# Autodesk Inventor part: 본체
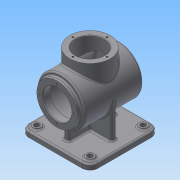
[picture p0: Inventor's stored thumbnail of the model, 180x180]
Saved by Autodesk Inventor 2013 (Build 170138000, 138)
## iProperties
Created: 2015-07
Part Number: 본체
Material: 일반
Document SubType Name: Modeling
Designer: ST5
Density: 1 g/cm^3
Author: ST5
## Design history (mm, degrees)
sketch "스케치1"
  geometry: L1 (-65, 65)-(65, 65); L2 (65, 65)-(65, -65); L3 (65, -65)-(-65, -65); L4 (-65, -65)-(-65, 65); 1 further point
  constraints: 8 end point, 2 parallel, 1 horizontal, 1 perpendicular
  dimensions: "d0" = 130 distance of L1.start L1.end; "d2" = 130 distance of L3.end L1.start; "d3" = 65 distance from line of point (0, 0) L1; "d4" = 65 distance from line of point (0, 0) L4
extrude "돌출1" new body sketch "스케치1" distance "d5" = 10; taper "d6" = 0 deg
node "작업 평면1"
sketch "스케치2"
  geometry: L1 (0, 0)-(0, 78); C1 r 45 at (0, 78)
  constraints: 2 end point, 1 centre point, 1 coincident, 1 vertical
  dimensions: "d8" = 78 distance of L1.start L1.end; "d9" = 90 diameter of C1
extrude "돌출2" join sketch "스케치2" stored distance "d10" = 110; taper "d11" = 0 deg
node "작업 평면2"
sketch "스케치3"
  geometry: L1 (-5, 45)-(5, 45); L2 (5, 45)-(5, -45); L3 (5, -45)-(-5, -45); L4 (-5, -45)-(-5, 45); L5 (-45, 5)-(45, 5); L6 (45, 5)-(45, -5); L7 (45, -5)-(-45, -5); L8 (-45, -5)-(-45, 5); 1 further point
  constraints: 16 end point, 4 parallel, 2 horizontal, 2 perpendicular
  dimensions: "d13" = 10 distance of L1.start L1.end; "d15" = 10 distance of L5.end L6.end; "d16" = 5 distance from line of L5 point (0, 0); "d17" = 5 distance from line of L2 point (0, 0); "d18" = 90 distance of L1.end L2.end; "d19" = 45 distance from line of point (0, 0) L3; "d20" = 90 distance of L5.start L5.end; "d21" = 45 distance from line of point (0, 0) L8
extrude "돌출3" join sketch "스케치3" distance "d22" = 68; taper "d23" = 0 deg
sketch "스케치4"
  geometry: C1 r 45 at (0, 0) reference; C2 r 38 at (0, 0); 1 further point
  constraints: 1 centre point, 1 coincident
  dimensions: "d24" = 76 diameter of C2
extrude "돌출4" join sketch "스케치4" distance "d26" = 7; taper "d27" = 0 deg
fillet "모깎기1" dims "d28" = 15
fillet "모깎기2" dims "d29" = 3
sketch "스케치5"
  geometry: C1 r 7.5 at (50, 50); C2 r 7.5 at (50, -50); C3 r 7.5 at (-50, 50); C4 r 7.5 at (-50, -50); A1 r 12 centre (50, -50) between (50, -62) and (62, -50) reference; A2 r 12 centre (50, 50) between (62, 50) and (50, 62) reference; A3 r 12 centre (-50, 50) between (-50, 62) and (-62, 50) reference; A4 r 12 centre (-50, -50) between (-62, -50) and (-50, -62) reference; 1 further point
  constraints: 4 centre point, 4 coincident
  dimensions: "d31" = 15 diameter of C1; "d33" = 15 diameter of C3; "d34" = 15 diameter of C4; "d35" = 15 diameter of C2
extrude "돌출5" join sketch "스케치5" distance "d36" = 3; taper "d37" = 0 deg
fillet "모깎기3" dims "d38" = 3
sketch "스케치6"
  geometry: C1 r 7.5 at (0, 0) reference; C2 r 5 at (0, 0); 1 further point
  constraints: 1 centre point, 1 coincident
  dimensions: "d39" = 10 diameter of C2
extrude "돌출6" cut sketch "스케치6" distance "d41" = 13; taper "d42" = 0 deg
sketch "스케치7"
  geometry: C1 r 7.5 at (0, 0) reference; C2 r 5 at (0, 0); 1 further point
  constraints: 1 centre point, 1 coincident
  dimensions: "d43" = 10 diameter of C2
extrude "돌출7" cut sketch "스케치7" distance "d45" = 13; taper "d46" = 0 deg
node "작업 평면4"
fillet "모깎기4" dims "d48" = 3
fillet "모깎기5" dims "d49" = 3
fillet "모깎기6" dims "d50" = 3
fillet "모깎기7" dims "d51" = 3
fillet "모깎기8" dims "d52" = 3
fillet "모깎기9" dims "d53" = 3
sketch "스케치8"
  geometry: C1 r 38 at (0, 0) reference; C2 r 27 at (0, 0); 1 further point
  constraints: 1 centre point, 1 coincident
  dimensions: "d54" = 54 diameter of C2
extrude "돌출8" cut sketch "스케치8" distance "d56" = 14; taper "d57" = 0 deg
node "작업 평면6"
sketch "스케치12"
  geometry: C1 r 40 at (0, 78); 1 further point
  constraints: 1 centre point
  dimensions: "d64" = 80 diameter of C1; "d66" = 0 horizontal distance of point (0, 0) C1.centre; "d67" = 78 distance of point (0, 0) C1.centre
extrude "돌출10" cut sketch "스케치12" stored distance "d68" = 96; taper "d69" = 0 deg
fillet "모깎기10" dims "d70" = 3
node "작업 평면7"
sketch "스케치13"
  geometry: 1 further point
node "작업 평면8"
sketch "스케치14"
  geometry: C1 r 38 at (0, 0); 1 further point
  constraints: 1 centre point, 1 coincident
  dimensions: "d78" = 76 diameter of C1
extrude "돌출11" join sketch "스케치14" stored distance "d80" = 96; taper "d81" = 0 deg
fillet "모깎기11" dims "d82" = 3
sketch "스케치15"
  geometry: C1 r 38 at (0, 0) reference; C2 r 27 at (0, 0)
  constraints: 1 centre point, 1 coincident
  dimensions: "d83" = 54 diameter of C2
extrude "돌출12" cut sketch "스케치15" distance "d85" = 50; taper "d86" = 0 deg
chamfer "모따기1" distance "d87" = 1; stored, may be unused: second distance "d88" = 2, angle "d89" = 45 deg
chamfer "모따기2" distance "d90" = 1; stored, may be unused: second distance "d91" = 2, angle "d92" = 45 deg
sketch "스케치16" dims "d95" = 64
  geometry: L1 (0, 0)-(0, 71.782); C1 r 28 at (0, 0) reference; 1 further point
  constraints: 2 end point, 1 coincident, 1 point on line, 1 vertical, 1 vertical alignment, 2 other
hole "구멍1" sketch "스케치16" at (0, 32) diameter "d97" = 3.242; stored, may be unused: countersink angle "d101" = 90 deg, drill point angle "d103" = 118 deg; dims "d98" = 8, "d99" = 4, "d100" = 2, "d102" = 10
sketch "스케치17" dims "d107" = 64
  geometry: L1 (0, 0)-(0, 73.386); C1 r 28 at (0, 0) reference; 2 further points
  constraints: 2 end point, 1 coincident, 1 point on line, 1 vertical, 1 vertical alignment, 2 other
hole "구멍2" sketch "스케치17" at (0, 32) diameter "d109" = 3.242; stored, may be unused: countersink angle "d113" = 90 deg, drill point angle "d115" = 118 deg; dims "d110" = 8, "d111" = 4, "d112" = 2, "d114" = 10
sketch "스케치18"
  geometry: L1 (1.889, 3.602)-(-1.889, 3.602); L2 (-1.889, 3.602)-(-1.889, -3.602); L3 (-1.889, -3.602)-(1.889, -3.602); L4 (1.889, -3.602)-(1.889, 3.602); L5 (-1.889, 0)-(1.889, 0); L6 (0, -3.602)-(0, 3.602); C1 r 42 at (0, 0) reference; 1 further point
  constraints: 4 end point, 2 other
  dimensions: "d119" = 0 distance from line of C1.centre L5; "d120" = 0 distance from line of L6 C1.centre
feature "엠보싱1" sketch "스케치18" dims "d15" = 10, "d16" = 5, "d20" = 90, "d21" = 45, "d121" = 0.5, "d122" = 0
node "솔리드1"
mirror "대칭1"
pattern_circular "원형 패턴1" dims angle "d105" = 360 deg
pattern_circular "원형 패턴2" dims angle "d117" = 360 deg
other parameters: "d7" = 0, "d47" = 0, "d63" = 0, "d71" = 0
